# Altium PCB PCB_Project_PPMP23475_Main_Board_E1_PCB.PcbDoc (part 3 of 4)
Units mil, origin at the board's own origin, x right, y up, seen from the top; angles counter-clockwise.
Board outline 10826.77 x 2559.06 mil, 6 copper layers (Top Layer, Signal Layer 1, Signal Layer 2, Signal Layer 3, Signal Layer 4, Bottom Layer), stack 65.535 mil thick; 162 components, 91 nets, 425 pads, 676 vias.
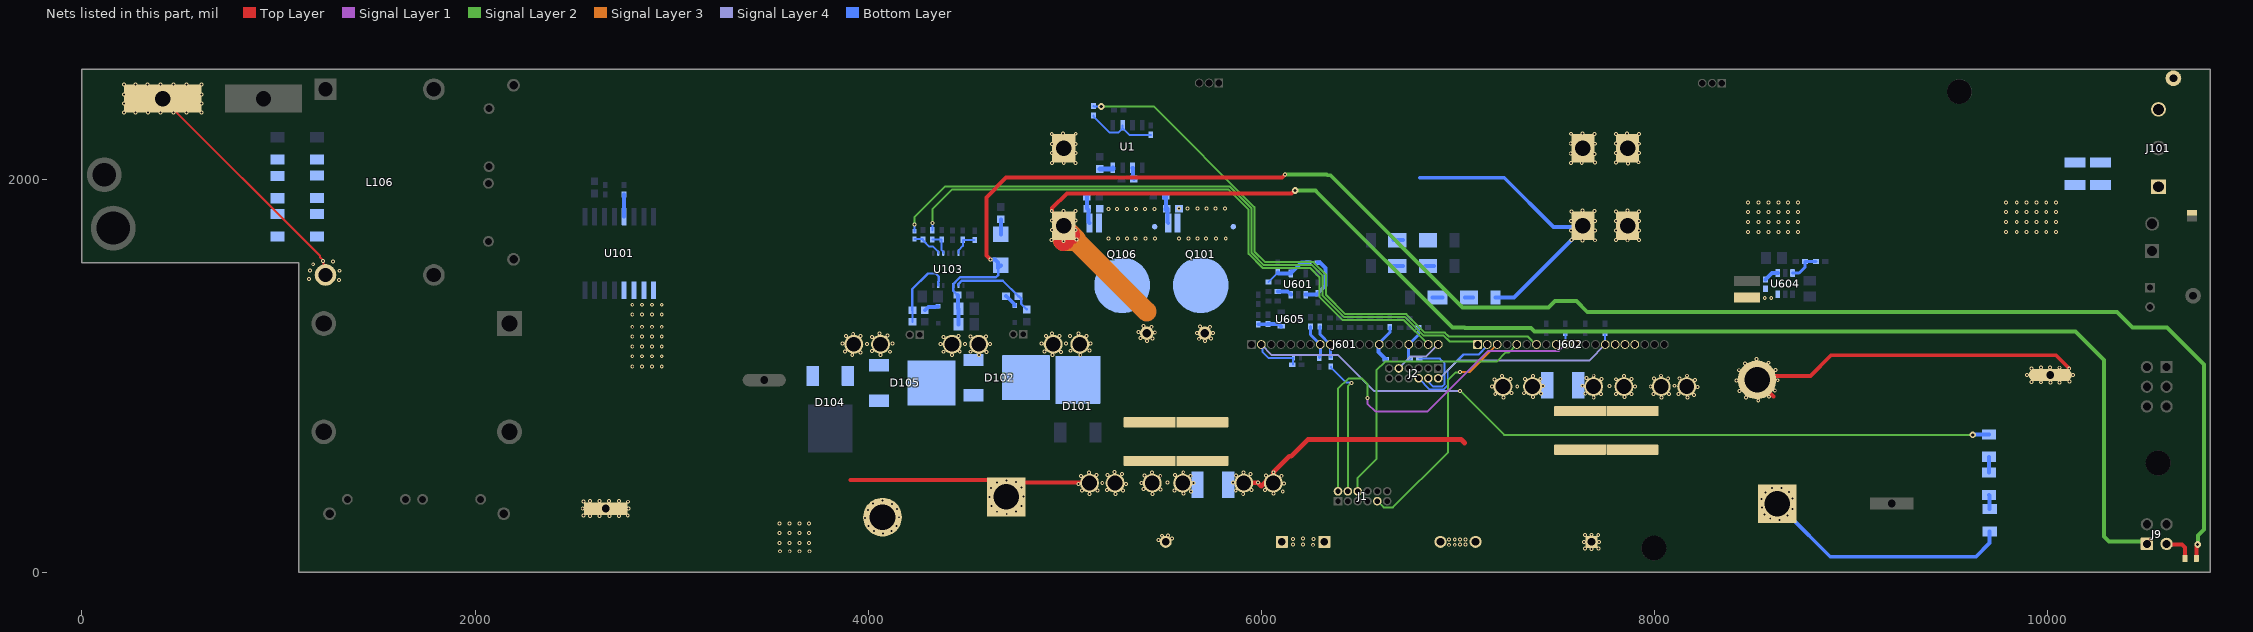
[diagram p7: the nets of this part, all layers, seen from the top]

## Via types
v1: diameter 20, hole 10, Top Layer to Bottom Layer, 563 vias
v2: diameter 20, hole 10, Top Layer to Bottom Layer, tented both sides, 103 vias
v3: diameter 34, hole 16, Top Layer to Bottom Layer, 10 vias

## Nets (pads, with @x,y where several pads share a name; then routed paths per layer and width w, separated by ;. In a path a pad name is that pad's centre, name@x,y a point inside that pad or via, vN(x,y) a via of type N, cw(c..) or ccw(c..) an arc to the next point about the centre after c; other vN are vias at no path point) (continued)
LS_TEMP1: J1.4 R623.1 | length 700.3
  Signal Layer 2 w10: J1.4@6440,413 6440,947 v2(6458,965)
  Bottom Layer w10: R623.1@6354,1048.38 6354,1044.44 6433,965.44 6457.56,965.44 v2(6458,965)
LS_TEMP2: J2.4 R637.1 | length 359.9
  Bottom Layer w10: R637.1@6803.62,1088 6908.49,1088 6933.05,1063.44 6933.05,958.76 6921.28,947 6872.72,947 6856.52,963.19 6856.52,981.48 J2.4@6850,988
LS_ZVS1: C612.1 J1.2 J602.10 | length 2044.2
  Signal Layer 1 w10: v1(6540,888) 6540,859 6581,818 6845.28,818 7155.21,1127.93 7513.27,1127.93 7545.32,1159.97 J602.10@7550,1159.97
  Signal Layer 2 w10: J1.2@6390,413 6390,934 6444,988 6512,988 6540,960 v1(6540,888) ; J602.10@7550,1150 J602.10@7550,1159
  Bottom Layer w10: C612.1@7547,1218.38 7548.5,1216.88 7548.5,1161.47 J602.10@7550,1159.97
  Bottom Layer w15: J602.10@7550,1159 J602.10@7550,1159.97
LS_ZVS2: C616.1 J2.2 J602.14 | length 981.4
  Signal Layer 4 w10: J2.2@6900,988 6907.07,988 6997.07,1078 7668.03,1078 J602.14@7750,1159.97
  Bottom Layer w10: C616.1@7748,1218.38 7749,1217.38 7749,1160.97 J602.14@7750,1159.97
  Bottom Layer w15: J602.14@7750,1159 J602.14@7750,1159.97
N_Wire: L106.2 pad.2 R112.1 R113.1 | length 1251.9
  Top Layer w10: pad.2@412.19,2411 1211.38,1611.81 1211.38,1603.32 1227,1587.71 v1(1227,1585) 1228.91,1583.09 1228.91,1498.06 L106.2@1229.41,1497.56
  other v1: 1309,1489 1155,1494 1310,1535 1160,1536 1177,1568 1277,1581 215,2340 273,2340 336,2340 401,2340 466,2340 533,2340 609,2340 215,2385 609,2385 215,2431 609,2432 215,2482 273,2482 335,2482 401,2482 466,2482 533,2482 609,2482
NetC115_1: C115.1 U101.13 | length 113.8
  Bottom Layer w20: C115.1@2758,1923.38 2759,1922.38 U101.13@2759,1810.01
NetC122_1: C122.1 R118.1 U103.2 | length 158.1
  Bottom Layer w10: R118.1@4235,1696.31 4277.06,1696.31 C122.1@4279,1694.38 4279,1690.44 4311.69,1657.75 4330.03,1657.75 4356.82,1630.96 U103.2@4356.82,1624.07
NetC123_1: C123.1 R120.1 U103.3 | length 122.2
  Bottom Layer w10: R120.1@4326,1693.38 4373,1693.38 C123.1@4374,1694.38 4374,1639.37 4382.41,1630.96 U103.3@4382.41,1624.07
NetC127_1: C127.1 R121.2 U103.6 | length 138.2
  Bottom Layer w10: U103.6@4459.18,1624.07 4459.18,1630.96 4460.09,1631.87 4460.09,1639.72 4482,1661.63 C127.1@4482,1692.38 4483,1691.38 R121.2@4542,1691.38
NetC128_1: C128.1 R122.1 U1.2 | length 369.1
  Bottom Layer w10: R122.1@5146,2325.38 5146,2321.44 5229.73,2237.71 5273.19,2237.71 U1.2@5295,2259.52 ; U1.2@5295,2275.27 U1.2@5295,2259.52 ; C128.1@5438,2226.38 5328.14,2226.38 U1.2@5295,2259.52
NetC623_1: C623.1 L601.1 U604.6
  other v2: 8561,1397 8594,1397
NetC623_2: C623.2 U604.1 | length 76.1
  Bottom Layer w20: C623.2@8565,1490.62 8597.51,1523.13 U604.1@8627.6,1523.13
NetD103_1: D103.1 R102.1 | length 66.3
  Bottom Layer w20: R102.1@4701.5,1406 4702.49,1406 4743.19,1365.3 4743.19,1360.12 D103.1@4745,1358.31
NetD106_1: D106.1 R111.1 | length 74.4
  Bottom Layer w20: R111.1@4288.5,1334 4289.48,1334 4306.01,1350.53 4343.74,1350.53 4345.71,1352.5 D106.1@4355.19,1352.5
NetD107_2: D107.2 R117.1 | length 76.8
  Bottom Layer w20: D107.2@4675,1719.74 R117.1@4675,1796.5
NetJ9_2: J9.2 R1.1 | length 157.7
  Top Layer w20: J9.2@10605,145.5 10607.5,143 10684.46,143 10699.46,128 R1.1@10699.46,72
NetQ101_1: Q101.1 R103.2 R104.2 | length 160.8
  Bottom Layer w20: R104.2@5505,1908.5 R104.2@5513.5,1917 5516,1914.5 5516,1848.5 R103.2@5516.5,1848 ; R103.2@5518.5,1850 5522.57,1845.93 5522.57,1781.7 Q101.1@5526.65,1777.63
  Bottom Layer w30: R103.2@5516.5,1848 R103.2@5518.5,1850
NetQ106_1: Q106.1 R101.2 R106.2 | length 140.2
  Bottom Layer w20: R101.2@5112.5,1912 5113.5,1911 5113.5,1851 R106.2@5114.5,1850 5120.9,1843.61 5120.9,1783.38 Q106.1@5126.65,1777.63
NetR102_2: R102.2 R105.2 U103.9 | length 437.4
  Bottom Layer w12: U103.9@4459.18,1460.69 4459.18,1467.39 4467.76,1475.97 4467.76,1476.79 4475.45,1484.48 4685.03,1484.48 4763.51,1406 R102.2@4764.5,1406 4765.48,1406 4778.18,1393.3 4778.18,1367.3 4806,1339.48 R105.2@4806,1338.5
NetR107_1: R107.1 R109.2
NetR108_1: R108.1 R110.2
NetR109_1: R109.1 R112.2
NetR110_1: R110.1 R113.2
NetR111_2: R111.2 R114.2 U103.12 | length 388.5
  Bottom Layer w12: R114.2@4225.5,1275 R111.2@4225.5,1334 4223.37,1336.13 4223.37,1440.63 4303.75,1521 4343.6,1521 4360,1504.6 4360,1481.4 4356.91,1478.32 4356.91,1460.78 U103.12@4356.82,1460.69
NetR119_2: R119.2 U1.6 | length 59.4
  Bottom Layer w20: U1.6@5345,2058.73 5346.81,2056.92 5346.81,2006.69 R119.2@5351.5,2002
NetR601_1: R601.1 R611.2 U601.1 | length 261.3
  Bottom Layer w20: U601.1@6225.4,1413.35 6280.24,1413.35 R611.2@6287,1420.11 6327,1460.11 6327,1548.49 6299,1576.49 R601.1@6286.62,1576.49
NetR601_2: R601.2 R609.2 R610.1 U601.4 | length 251
  Bottom Layer w10: R610.1@6036.38,1477.49 R609.2@6084,1525.11
  Bottom Layer w20: R609.2@6084,1525.11 6087.49,1521.62 U601.4@6150.6,1521.62 ; U601.4@6150.6,1522.18 6150.6,1529.5 6152.41,1531.31 6159.73,1531.31 6204.91,1576.49 R601.2@6239.38,1576.49
NetR602_1: R602.1 R606.2 | length 43.2
  Bottom Layer w20: R606.2@7035.09,1399 7076.91,1399 R602.1@7077.91,1400
NetR603_1: R603.1 R607.2 | length 42.8
  Bottom Layer w20: R607.2@6835.09,1559 R603.1@6877.91,1559
NetR604_1: R604.1 R608.2
NetR606_1: R606.1 R612.2 | length 49.8
  Bottom Layer w20: R612.2@6871.09,1399 R606.1@6920.91,1399
NetR607_1: R607.1 R613.2 | length 49.8
  Bottom Layer w20: R613.2@6671.09,1559 R607.1@6720.91,1559
NetR608_1: R608.1 R614.2 | length 49.8
  Bottom Layer w20: R614.2@6671.09,1691 R608.1@6720.91,1691
NetR616_1: R616.1 U601.3 | length 73.7
  Bottom Layer w20: R616.1@6083.62,1429.49 6134.46,1429.49 U601.3@6150.6,1413.35
NetR621_1: R621.1 R622.2 | length 73.1
  Bottom Layer w20: R622.2@9702,393.91 9705,390.91 R621.1@9705,322.09
NetR622_1: R622.1 R624.2 | length 83.7
  Bottom Layer w15: R624.2@9702,588.91 R624.2@9704,586.91
  Bottom Layer w20: R622.1@9702,508.09 R624.2@9702,588.91
NetR640_1: R640.1 R642.2 U605.1 | length 121
  Bottom Layer w20: R642.2@5985,1262.87 6033,1262.87 R640.1@6034,1263.87 6088.98,1263.87 U605.1@6100.76,1252.09
NetR641_1: R641.1 R643.2 U604.3 | length 160.6
  Bottom Layer w15: U604.3@8702.4,1523.13 8736.13,1523.13 8765.62,1552.62 R643.2@8765.62,1582 R641.1@8821.38,1582
Neutral: C106.1 C110.1 C124.1 D102.1 D102.3 D105.2 N_LF_1.1 N_LF_2.1 U101.1 U101.2 U101.3 U101.4 | length 2.8
  Bottom Layer w25: C106.1@6103.28,163 C106.1@6105.28,165
  other v1: 7679,119 7647,122 7715,122 6264,141 6161,142 6211,142 7642,155 7718,156 6161,170 6265,171 6212,172 7646,190 7714,190 7679,192 4564,1106 4427,1107 4602,1121 4384,1123 4521,1123 4466,1125 4368,1162 4492,1163 4620,1163 4383,1198 4521,1200 4599,1200 4459,1203
  other v2: 3551,108 3601,108 3651,108 3701,108 3550,150 3600,150 3650,150 3700,150 3550,200 3600,200 3650,200 3700,200 3550,250 3600,250 3650,250 3700,250 2800,1049 2850,1049 2900,1049 2950,1049 2800,1100 2850,1100 2900,1100 2950,1100 2800,1150 2850,1150 2900,1150 2950,1150 2800,1200 2850,1200 2900,1200 2950,1200 2800,1250 2850,1250 2900,1250 2950,1250 2800,1312 2850,1312 2900,1312 2950,1312 2800,1362 2850,1362 2900,1362 2950,1362
PFCG_1H: J1.9 J602.3 | length 1182.4
  Signal Layer 2 w10: J1.9@6590,363 6622.05,330.95 6668.95,330.95 6950,612 6950,980.28 6986.8,1017.09 7009.09,1017.09 v1(7011,1019)
  Signal Layer 3 w10: v1(7011,1019) 7059.03,1019 J602.3@7200,1159.97
PFCG_1L: J1.6 J602.5 | length 1424
  Signal Layer 2 w10: J1.6@6490,413 6490,482 6584.95,576.95 6584.95,1027.95 6630,1073 7196.72,1073 7241.72,1118 7258.03,1118 J602.5@7300,1159.97
PFCG_2H: J2.9 J601.20 | length 250.5
  Signal Layer 4 w10: J2.9@6700,1038 6760.99,1098.99 6839.01,1098.99 J601.20@6900,1159.97
PFCG_2L: J2.6 J602.2 | length 527.2
  Signal Layer 4 w10: J602.2@7143.48,1152.48 J602.2@7150,1159
  Bottom Layer w10: J2.6@6800,988 6858,930 6925.5,930 6948.5,953 6948.5,1028.99 7028.5,1109 7106.1,1109 7150,1152.9 J602.2@7150,1159.97
PGND: C2.1 C3.1 C4.1 C5.1 C101.1 C102.1 C130.2 C131.2 D104.1 D104.3 D105.1 D105.3 J101.1 NT1.1 pad.1@4994.89,2157.61 pad.1@7635.89,2158 pad.1@7863.11,2158 PGND_LF_1.1 PGND_LF_2.1 PGND_PH1_1.1 PGND_PH1_2.1 PGND_PH2_1.1 PGND_PH2_2.1
  other v1: 5446,400 5604,402 5643,412 5559,418 5487,423 5400,424 5654,455 5390,456 5522,457 5486,492 5639,492 5406,494 5562,495 5443,509 5603,510 7691,891 7848,892 7729,908 7884,908 7805,909 7648,910 7900,947 7771,948 7634,950 7804,983 7730,985 7884,985 7655,989 7846,1000 7691,1001 3919,1107 4062,1107 3960,1120 4110,1123 3883,1124 4020,1126 3995,1163 3870,1165 4123,1165 4019,1197 3888,1202 3960,1202 4098,1206 3924,1214 4058,1215 8475,1733 8530,1733 8580,1733 8630,1733 8680,1733 8730,1733 9788,1733 9843,1733 9893,1733 9943,1733 9993,1733 10043,1733 8475,1783 8530,1783 8580,1783 8630,1783 8680,1783 8730,1783 9788,1783 9843,1783 9893,1783 9943,1783 9993,1783 10043,1783 8475,1833 8530,1833 8580,1833 8630,1833 8680,1833 8730,1833 9788,1833 9843,1833 9893,1833 9943,1833 9993,1833 10043,1833 8475,1883 8530,1883 8580,1883 8630,1883 8680,1883 8730,1883 9788,1883 9843,1883 9893,1883 9943,1883 9993,1883 10043,1883 7865,2081 7630,2082 4995,2083 5055,2083 4935,2084 7576,2084 7697,2085 7805,2086 7919,2087 7696,2130 7574,2131 7804,2134 7922,2134 4934,2135 5056,2135 4935,2179 5056,2180 7697,2181 7922,2181 7574,2182 7804,2182 7695,2230 7922,2230 4934,2231 7805,2231 5056,2232 7575,2232 4992,2233 7634,2233 7861,2234
PRI_FAULT: J602.15
PWM1A: J601.19 R120.2 | length 3189.9
  Signal Layer 2 w10: v1(4327,1777) 4327,1849 4427,1949 5832,1949 5935,1846 5935,1620.57 6006.57,1549 6248.7,1549 6295.56,1502.14 6295.56,1403.44 6414.84,1284.16 6725.81,1284.16 J601.19@6850,1159.97
  Bottom Layer w10: R120.2@4326,1740.62 4326.5,1741.12 4326.5,1776.5 v1(4327,1777)
PWM1B: J602.1 R118.2 | length 3526.3
  Signal Layer 2 w10: v1(4235,1771) 4235,1807 4392,1964 5824.79,1964 5838.21,1964 5950,1852.21 5950,1838.79 5950,1626.79 6012.79,1564 6258.33,1564 6310.56,1511.76 6310.56,1409.65 6421.05,1299.16 6732.02,1299.16 6826.19,1205 6927.89,1205 6957.86,1175.04 7084.94,1175.04 J602.1@7100,1159.97
  Bottom Layer w10: R118.2@4235,1735.69 v1(4235,1771)
RELAY_CTRL: J602.7 R122.2 | length 2948.6
  Signal Layer 2 w10: v3(5186,2371) 5452.43,2371 5965,1858.43 5965,1633 6019,1579 6264.54,1579 6329,1514.54 6329,1412.43 6427.26,1314.16 6738.24,1314.16 6832.4,1220 6934.11,1220 6953.61,1200.5 7354.79,1200.5 7396.29,1159 J602.7@7400,1159
  Bottom Layer w10: R122.2@5146,2372.62 5147.62,2371 v3(5186,2371)
SCI_RX0: J602.16
SCI_TX0: J602.17 | length 9
  Signal Layer 2 w10: J602.17@7900,1159 J602.17@7900,1168
SDC: J602.9
SDD: J602.11
SW1: L1.1 L102.1 SW_PH1_1.1 SW_PH1_2.1 | length 1235.6
  Top Layer w20: 3910.41,471.59 4643.41,471.59 v1(4656,459) 4690.37,459 4702.96,471.59 4713.55,461 v1(4752,461) 4756,457 5104.05,457 SW_PH1_1.1@5122.05,439
  other v1: 2586,287 2684,287 2733,287 2633,288 2551,290 2777,290 4705,298 4656,309 4753,311 2781,325 2548,326 4627,338 4779,338 2778,360 2551,361 2633,363 2733,363 2586,364 2682,364 4617,384 4790,386 5127,400 5258,400 5088,417 5166,417 5296,417 5214,420 4625,430 4781,433 5311,450 5070,451 5191,455 4703,467 5083,490 5218,495 5161,497 5292,500 5124,509 5253,511
SW2: L2.2 L104.2 SW_PH2_1.1 SW_PH2_2.1 | length 1881.2
  Top Layer w20: 8606.15,895 8543.35,957.8 8543.35,999.65 8793.65,999.65 8899.07,1105.07 10042.93,1105.07 v1(10110,1038) 10100.51,1028.51 10100.51,1024.63 10080.65,1004.77 L2.2@10013.54,1004.77
  other v1: 8528,875 8036,891 8168,891 8466,891 8583,894 8201,904 7994,907 8123,908 8074,909 8433,923 8612,925 8218,944 7981,946 8103,950 10014,967 10061.3,966.74 9967.3,967.74 9917,970 10111,972 8417,976 8627,978 8207,980 7997,987 8070,987 8127,988 8033,1001 8166,1001 9896,1005 10130,1005 8429,1029 8615,1030 9917,1038 10013,1042 10060.3,1041.74 9966.3,1042.74 8460,1064 8581,1067 8520,1085
TEMP1: C608.1 J601.8 R620.2 | length 207.7
  Bottom Layer w15: C608.1@6250,1250.87 6250,1209.97 J601.8@6300,1159.97 J601.8@6300,1159 ; R620.2@6295,1092.62 6295,1096.56 6300,1101.56 J601.8@6300,1159 ; J601.8@6312.27,1160.61 6310,1158.35 6310,1149 J601.8@6300,1159
TEMP2: C610.1 J601.9 R623.2 | length 178.4
  Bottom Layer w15: C610.1@6298,1250.87 6298,1211.97 J601.9@6350,1159.97 6350,1159 6352,1157 6352,1097.62 R623.2@6354,1095.62
TEMP3: C613.1 J601.14 R626.2 | length 205.7
  Bottom Layer w15: J601.14@6600,1159 6600,1168 6654,1222 C613.1@6654,1248.87
  Bottom Layer w20: J601.14@6600,1159 6596.01,1155.01 6596.01,1122.37 6627.63,1090.75 6627.63,1086.81 6629.44,1085 R626.2@6633.38,1085
TEMP4: C615.1 J601.17 R637.2 | length 183.4
  Bottom Layer w15: R637.2@6756.38,1088 6753.81,1088 6749.5,1092.31 6749.5,1158.5 6750,1159 J601.17@6750,1159.97 6800.38,1210.35 C615.1@6800.38,1246
Vbulk: C2.2 C3.2 C4.2 C5.2 C130.1 C131.1 D101.2 D102.2 Q101.9 Q106.9 RT1.1 VB_LF_1.1 VB_LF_2.1 VB_PH1_1.1 VB_PH1_2.1 VB_PH2_1.1 VB_PH2_2.1 | length 1209
  Top Layer w25: 5962.5,456.5 5982.5,456.5 6000,439 6038.5,477.5 6064.16,477.5 6061,480.66 v1(6061,510) 6142.5,591.5 6152.5,591.5 6238.5,677.5 7015.77,677.5 7034.27,659
  other v1: 5908,400 6062,401 6109,411 5870,417 5951,419 6018,420 6116,452 5855,458 5984,458 6102,492 5871,493 6023,493 5944,500 5910,509 7232,891 7381,892 7190,908 7422,911 7337,912 7273,914 7174,946 7302,947 7434,948 7187,982 7268,984 7341,984 7419,985 7225,1000 7383,1000 4937,1106 5079,1106 4981,1121 4897,1124 5030,1128 5125,1130 5130,1165 4882,1166 5007,1166 5714,1177 5683,1189 5743,1191 4904,1203 4974,1203 5026,1203 5110,1203 5070,1215 4936,1216 5672,1218 5754,1218 5739,1250 5687,1251
Vbulk_out: C1.2 C101.2 C102.2 J9.1 J101.3 pad.1@4994.89,1763.91 pad.1@7635.89,1764.3 pad.1@7863.11,1764.3 Q101.2 Q101.3-4-5-6-7-8 Q106.2 Q106.3-4-5-6-7-8 R103.1 R106.1 R602.2 RT1.2 TP101.1 U1.8 | length 9391.1
  Top Layer w20: v1(4934,1838) 4934.75,1838.75 4934.75,1853.25 5010.51,1929 6154.21,1929 6168.21,1943 v3(6172,1943)
  Top Layer w25: J9.1@10502.5,143 J9.1@10505,145.5
  Top Layer w100: v1(4993,1685) 5021.51,1713.51 pad.1@5021.51,1723.51 ; pad.1@4994.89,1763.91 4994.89,1750.13 pad.1@5021.51,1723.51 ; pad.1@5026.51,1718.51 pad.1@5021.51,1723.51
  Signal Layer 2 w20: v3(6172,1943) 6275.28,1943 6287,1931.28 6287,1930.75 6972.25,1245.5 7033.5,1245.5 7036,1243 7372.4,1243 7388.78,1226.62 10141.38,1226.62 10287.5,1080.5 10287.5,182.5 10313,157 10493.5,157 J9.1@10505,145.5
  Signal Layer 3 w100: pad.1@4994,1751.02 pad.1@4994,1764.5 ; pad.1@4994.89,1763.91 4994.89,1750.13 5021.51,1723.51 5021.51,1719.51 4990,1688 v1(4993,1685) 5060.02,1685 5417,1328.02 ; pad.1@5025.5,1727.5 v1(5059,1694) ; pad.1@5026.51,1718.51 pad.1@5052.55,1692.48
  Bottom Layer w20: 6808,2008 7236,2008 7486,1758 7629.59,1758 pad.1@7635.89,1764.3 7635.89,1750.52 7577.74,1692.37 7284.37,1399 R602.2@7191.09,1399
  Bottom Layer w25: C1.2@5178,2052.5 5244.31,2052.5 5245,2053.19 U1.8@5245,2058.73
  other v1: 5418,1178 5447,1190 5386,1192 5458,1221 5376,1223 5442,1250 5401,1255 7633,1689 7697,1690 7863,1690 7578.72,1691.38 7804,1691 7922,1691 4933,1692 5222,1698 5270,1698 5316,1698 5359,1698 5411,1698 5460,1698 5581,1699 5629,1699 5675,1699 5718,1699 5770,1699 5819,1699 7575,1739 7697,1739 7804,1740 7921,1740 5056,1742 4935,1743 7804,1787 7922,1787 7575,1788 7697,1788 4934,1790 5056,1790 7577,1837 7804,1837 7922,1837 7696,1838 4994,1839 5055,1839 7633,1841 7862,1841 5222,1850 5265,1850 5317,1850 5362,1850 5408,1850 5456,1850 5581,1851 5624,1851 5676,1851 5721,1851 5767,1851 5815,1851
Vcb: C106.2 C110.2 C124.2 L102.2 L104.1 R621.2 | length 1203.1
  Bottom Layer w20: v1(8676,289) 8685.22,289 8894.22,80 9636,80 9705,149 R621.2@9705,207.91
  other v1: 6955.15,141 6984,141 7011.08,142 7039,142 5477,165 6955.15,167 6984,167 7011.08,168 7039,168 5546,173 5494,187 5525,189 4076,199 4029,211 4118,211 4001,236 4144,237 8637,268 8589,274 3985,278 4156,281 8560,295 3999,317 4146,323 8702,323 8546,331 4122,348 4025,350 4074,366 8545,374 8702,376 8564,407 8684,410 8597,429 8646,431
Vcb_SENSE: C624.2 J601.2 R624.1 R625.2 | length 4138.3
  Signal Layer 2 w10: v1(7011,924) 7235,700 v3(9619,700)
  Signal Layer 4 w10: J601.2@6000,1159.97 6053.94,1106.04 6390.96,1106.04 6573,924 v1(7011,924)
  Bottom Layer w10: J601.2@6000,1159.97 6005.21,1154.76 6005.21,1121.79 6037,1090 R625.2@6162.97,1090 ; C624.2@6161.16,1057.81 6161.16,1088.19 R625.2@6162.97,1090 ; R625.2@6163.28,1090 R625.2@6162.97,1090
  Bottom Layer w20: v3(9619,700) 9628,700 9631.09,703.09 R624.1@9702,703.09
VDDB: C116.1 C118.1 C119.2 D107.1 R1.2 U103.10 | length 8590.2
  Top Layer w20: v1(4622,1592) 4601,1613 4601,1908 4702,2009 6106.54,2009 v1(6121.54,2024) ; R1.2@10756.54,72 10756.54,131.75 10763,138.21 v3(10763,142) v3@10762,143
  Signal Layer 2 w20: v1(6121.54,2024) 6333,2024 6336,2021 6350.89,2021 7022.89,1349 7461,1349 7493,1381 7603,1381 7658,1326 10352,1326 10432,1246 10608,1246 10795,1059 10795,217.79 10765.68,188.47 10765.68,144.68 v3(10763,142)
  Bottom Layer w12: C119.2@4454.5,1412 4453.52,1412 4440.82,1424.7 4440.82,1425.69 4433.59,1432.91 U103.10@4433.59,1460.69 4433.59,1467.39 4442.17,1475.97 4442.17,1476.79 4466.86,1501.48 4650.48,1501.48 4660.92,1511.92 D107.1@4660.92,1548.18
  Bottom Layer w20: C119.2@4454.5,1412 4457.25,1409.25 4457.25,1343.75 C116.1@4460,1341 C118.1@4460,1262 ; v1(4622,1592) 4622.37,1591.63 4645.63,1591.63 4660.92,1576.34 4660.92,1548.18 D107.1@4675,1562.26
pads on no net: J01.1 J01.2 J01.3 J3.1 J3.2 J3.3 J101.2 J601.3 J601.4 J601.5 J601.7 J602.13 J602.20 U101.9 U101.11 U101.14 U101.16 U103.5

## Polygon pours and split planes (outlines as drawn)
5VP on Top Layer "Top Layer-No Net 14" (solid, remove dead copper, pour order 981): 19 vertices, not listed, extent 5844,876 10544,1574.8
Vbulk on Top Layer "Top Layer-No Net 3" (solid, pour order 913): 28 vertices, not listed, extent 4814,332 8051,1314
Vbulk_out on Top Layer "Top Layer-No Net" (solid, remove dead copper, pour order 989): 20 vertices, not listed, extent 4911,1149.58 10785,2559.06
12VP on Top Layer "NONET_L-01_P-001" (solid, pour order 1038): 4680,1913 4661,1894 4661,1591.71 4626.29,1557 4345,1557 4322,1534 4322,1455 4349,1428 4737,1428 4813,1504 4813,1866.47 4755.97,1913
Neutral on Top Layer "Top Layer-No Net 4" (solid, pour order 998): 3640,751 3787,604 4646,604 4646,1365 4378,1365 3992,1751 2783,1751 2783,1032.28 3278.96,1032.28 3278.96,1084 3598,1084 3640,1042
AGND on Top Layer "Bottom Layer-No Net 22" (solid, pour order 1004): 10325,1617 10518,1810 10795,1810 10795,1286 10795,804 10546.47,804 10546.47,1069.47 10494.94,1121 10325,1121
PGND on Top Layer "Bottom Layer-No Net 23" (solid, pour order 985): 5809,575 5780,604 5368,604 5347,583 5347,382 5397,332 5734,332 5809,407
PGND on Top Layer "Top Layer-No Net 17" (solid, pour order 984): 7997.5,845.5 7921,922 7921,1027 7483,1027 7483,790 7997.5,790
SW2 on Top Layer "Top Layer-No Net 2" (solid, remove dead copper, pour order 917): 9920,1266 8442,1266 8224,1048 8033,1048 7961,976 7961,859 8056,764 8721,764 8868,911 10110,911 10162,963 10162,1024
Neutral on Top Layer "Top Layer-No Net 19" (solid, pour order 1082): 3530.6,84 3530.6,270.43 3732,270.43 3732,84
AC_N1 on Top Layer "Top Layer-No Net 19" (solid, pour order 1081): 2578.6,1092 2578.6,1373.43 2717.6,1373.43 2717.6,1092
PGND on Top Layer "Top Layer-No Net 19" (solid, pour order 1080): 3860.61,1226 4119.61,1226 4119.61,1087 3860.61,1087
PGND on Top Layer "Bottom Layer-No Net 22" (solid, pour order 1014): 10301,1539 10301,1629 10491,1819 10760,1819 10793,1852 10793,2015 10769,2039 8612,2039 8430,1857 8430,1681 8463,1648 8858,1648 8967,1539
PGND on Top Layer "Top Layer-No Net 15" (solid, pour order 1003): 5339,2054 5408.77,2123.77 6313.23,2123.77 6428,2009 7889,2009 7988,2108 7988,2413 7892,2509 4891,2509 4891,2054
AC_L1 on Top Layer "Top Layer-No Net 5" (solid, remove dead copper, pour order 918): 21 vertices, not listed, extent 1145,212 3603,1092
SW1 on Top Layer "Top Layer-No Net 1" (solid, remove dead copper, pour order 916): 5317.58,381.28 5316.98,497.66 5241.64,573 3756.34,573 3088.5,573 2484,573 2484,53 3236.34,53 3505.34,322 3916.95,322 4012.98,418.02 4139.98,418.02 4236,322 5258.3,322
Vcb on Top Layer "Top Layer-No Net 11" (solid, remove dead copper, pour order 959): 24 vertices, not listed, extent 3973,5 8765,553
Neutral on Top Layer "Top Layer-No Net 19" (solid, pour order 915): 6091,185 6325,185 6341,169 6341,137 6328,124 6096,124 6082,138 6082,176
N_Wire on Top Layer "Top Layer-No Net 6" (solid, remove dead copper, pour order 919): 25 vertices, not listed, extent 101,1423 1341,2514
L_Wire on Top Layer "Top Layer-No Net 7" (solid, remove dead copper, pour order 920): 1291,2543 1355,2479 1355,2298 1267,2210 849,2210 720,2339 720,2514 749,2543
AC_N on Top Layer "Top Layer-No Net 8" (solid, remove dead copper, pour order 931): 2133,1747 1767,1747 1715,1695 1715,1398 1765,1348 1948,1165 2290,1165 2348,1223 2348,1532
AC_L on Top Layer "Top Layer-No Net 9" (solid, remove dead copper, pour order 932): 19 vertices, not listed, extent 1131,1111 2239.5,2536
AC_N1 on Top Layer "Top Layer-No Net 16" (solid, pour order 982): 2000,712 2000,300 2050,250 2214,250 2272,308 2272,708 2202,778 2066,778
AC_L1 on Top Layer "Top Layer-No Net 20" (solid, pour order 1024): 9148,465 9606,465 9606,131 9121,131 9060,192 9060,377
Neutral on Top Layer "Signal Layer 1-No Net 3" (solid, pour order 914): 7628.5,218 7744.5,218 7744.5,103 7628.5,103
NetC623_1 on Top Layer "Top Layer-No Net 13" (solid, pour order 964): 8404,1427 8595,1427 8605,1417 8605,1376 8595,1366 8406,1366 8396,1376 8396,1419
EARTH on Top Layer "Top Layer-No Net 10" (solid, remove dead copper, pour order 954): 34,2114 151,2114 205,2060 205,1878 281,1802 281,1678 205,1602 33,1602 6,1629 6,2085
AC_L1 on Bottom Layer "Bottom Layer-No Net" (solid, pour order 986): 24 vertices, not listed, extent 3299,123 9612,1057
AGND on Bottom Layer "NONET_L-01_P-001" (solid, pour order 1084): 6830,1242 7834,1242 7941,1135 7974,1135 7974,1237 7893,1318 6830,1318
Vbulk_out on Bottom Layer "Bottom Layer-No Net 6" (solid, pour order 991): 21 vertices, not listed, extent 4871,1620 10790,2559.05
AGND on Bottom Layer "NONET_L-01_P-001" (solid, pour order 1025): 2445,2540 2445,1574.8 4894,1574.8 4894,2265.06 5113,2265.06 5113,2227.88 5503.5,2227.88 5502.83,2540
Vbulk_out on Bottom Layer "Signal Layer 4-No Net" (solid, pour order 1083): 5338,1285 5338,1149.58 5501,1149.58 5501,1285
EARTH on Bottom Layer "Bottom Layer-No Net 20" (solid, pour order 1075): 6,2135.5 267,2135.5 267,1626 6,1626
SW1 on Bottom Layer "Bottom Layer-No Net 23" (solid, pour order 1051): 2801,388 2525,388 2525,266 2801,266
AGND on Bottom Layer "Bottom Layer-PGND" (solid, pour order 1023): 33 vertices, not listed, extent 8613,1283 10795,1819
PGND on Bottom Layer "NONET_L-01_P-001" (solid, pour order 1020): 3651,975 3651,1244 4136,1244 4136,801 3825,801
Neutral on Bottom Layer "Bottom Layer-Neutral" (solid, remove dead copper, pour order 1045): 19 vertices, not listed, extent 2737,15 7776,1493
Vbulk on Bottom Layer "Bottom Layer-No Net 24" (solid, pour order 978): 5831,528 6109,528 6133,504 6133,375 5844.06,375 5809,410.06 5809,506
5VP on Bottom Layer "NONET_L-01_P-001" (solid, pour order 1037): 5266,2364.69 5260.53,2371 5226.62,2371 5226.62,2370.62 5202,2346 5202,2289 5237.97,2253.03 5257.03,2253.03 5266,2262
Vcb on Bottom Layer "Bottom Layer-No Net 27" (solid, pour order 1009): 8430,474 8729,474 8766,437 8766,199.5 8683,116.5 8413.5,116.5 8363,167 8363,407
12VP on Bottom Layer "NONET_L-01_P-001" (solid, pour order 1028): 8658.19,1436.98 8824.02,1436.98 8832,1429 8832,1344 8819,1331 8657,1331 8640,1348 8640,1433
PGND on Bottom Layer "Bottom Layer-PGND" (solid, pour order 1022): 10408.93,1584 10408.93,1731.64 10505.28,1828 10795,1828 10795,1919 10706,2008 10501,2008 8582,2008 8415,1841 8415,1698 8465,1648 8858,1648 8951,1555 10381.03,1556.1
Vbulk on Bottom Layer "Bottom Layer-No Net 2" (solid, pour order 990): 5884,867 5884,1657 4776,1657 4776,1453 4841,1388 4841,1139.82 4698,996.82 4698,867
Neutral on Bottom Layer "NONET_L-01_P-001" (solid, pour order 1021): 4195,1100 4336,1100 4353,1117 4353,1198 4363,1208 4636,1208 4636,879.78 4554.28,809 4227.79,809 4148.35,888.44 4147.44,1052.44
AC_N1 on Bottom Layer "Bottom Layer-No Net 3" (solid, remove dead copper, pour order 922): 2535,1493 2481,1439 2481,1276 1961,756 1961,306 2058,209 2242,209 2295,262 2295,584 2725,1014 2725,1484 2716,1493
L_Wire on Bottom Layer "Bottom Layer-No Net 11" (solid, remove dead copper, pour order 929): 749,2543 1285,2543 1337,2491 1337,2286 1236,2185 876,2185 798,2263 720,2341 720,2514
N_Wire on Bottom Layer "Bottom Layer-No Net 12" (solid, remove dead copper, pour order 930): 23 vertices, not listed, extent 106,1410 1342,2515
AC_N on Bottom Layer "Top Layer-No Net 8" (solid, remove dead copper, pour order 957): 2133,1747 1767,1747 1715,1695 1715,1398 1765,1348 1949,1164 2266.36,1164 2348,1245.64 2348,1532
AC_L on Bottom Layer "Top Layer-No Net 9" (solid, remove dead copper, pour order 961): 19 vertices, not listed, extent 1131,1111 2239.5,2536
AC_L1 on Bottom Layer "Bottom Layer-No Net 20" (solid, pour order 962): 1185,824.5 1338,824.5 1405,757.5 1405,279.5 1341,215.5 1199,215.5 1144,270.5 1144,783.5
SW2 on Bottom Layer "Top Layer-No Net 2" (solid, remove dead copper, pour order 1012): 9973,1231 8307,1231 8124,1048 8003,1048 7961,1006 7961,885 8036,810 8767,810 10009,810 10162,963 10162,1042
PGND on Bottom Layer "Bottom Layer-No Net 23" (solid, pour order 972): 7915.72,1027 7602,1027 7544,969 7544,874 7914.67,874
Vbulk on Bottom Layer "Signal Layer 4-No Net" (solid, pour order 979): 7179,1033 7151,1005 7151,918 7194,875 7474,875 7474,968 7409,1033
SW2 on Bottom Layer "Bottom Layer-No Net 26" (solid, pour order 983): 8056,980 8087,1011 8347,1011 8375,983 8375,841 8345,811 8067,811 8056,822
Vcb on Bottom Layer "Bottom Layer-No Net 21" (solid, remove dead copper, pour order 921): 6891,176 7111,176 7111,134 6891,134
SW1 on Bottom Layer "Bottom Layer-No Net 25" (solid, pour order 980): 4668.12,524 4632,482.93 4632,361 4678,315 5244,315 5317.35,388.35 5317.35,497.29 5290.64,524
AGND on Bottom Layer "Bottom Layer-No Net 17" (solid, pour order 949): 6484,1225.16 6484,1145 6492,1137 6511.29,1137 6518.45,1144.16 6518.45,1183.61 6556,1221.16 6572,1237.16 6572,1309.16 6567,1314.16 6488,1314.16 6484,1310.16
5VP on Bottom Layer "Bottom Layer-No Net 15" (solid, pour order 940): 8510,1635 8414,1539 8414,1514 8425,1503 8519,1503 8539,1523 8539,1541 8553,1555 8587,1555 8595,1563 8595,1629 8589,1635
NetC623_1 on Bottom Layer "Bottom Layer-No Net 14" (solid, pour order 933): 8551,1459 8578,1459 8602,1435 8638,1435 8640,1433 8640,1396 8630,1386 8554,1386 8548,1392 8548,1456
NetR107_1 on Bottom Layer "Bottom Layer-No Net 10" (solid, remove dead copper, pour order 923): 1028,2129 1032,2125 1032,1993 1027,1988 963,1988 958,1993 958,2125 962,2129
NetR108_1 on Bottom Layer "Bottom Layer-No Net 10" (solid, remove dead copper, pour order 924): 1229,2129 1233,2125 1233,1993 1228,1988 1164,1988 1159,1993 1159,2125 1163,2129
NetR109_1 on Bottom Layer "Bottom Layer-No Net 10" (solid, remove dead copper, pour order 925): 1028,1934 1032,1930 1032,1798 1027,1793 963,1793 958,1798 958,1930 962,1934
NetR110_1 on Bottom Layer "Bottom Layer-No Net 10" (solid, remove dead copper, pour order 927): 1229,1934 1233,1930 1233,1798 1228,1793 1164,1793 1159,1798 1159,1930 1163,1934
PGND on Bottom Layer "Bottom Layer-No Net 23" (solid, pour order 974): 5715.56,525 5375,525 5375,370.56 5715.56,370.56
Vbulk on Signal Layer 2 "Signal Layer 2-No Net 2" (solid, pour order 977): 7171,1015 7426,1015 7464,977 7464,923 7413,872 7184,872 7151,905 7151,995
PGND on Signal Layer 2 "Bottom Layer-No Net 22" (solid, remove dead copper, pour order 971): 8431,2026 8055,1650 7531,1650 7451.81,1729.19 7451.81,1995.81 7512,2056 7925,2056 8002,2133 8002,2540 6597,2540 6597,1884 7051,1430 10805,1430 10805,1946 10725,2026
5VP on Signal Layer 2 "NONET_L-01_P-001" (solid, pour order 1029): 39 vertices, not listed, extent 2580.91,277 6484.13,2353
N_Wire on Signal Layer 2 "Bottom Layer-No Net 23" (solid, pour order 1078): 631,2321.77 631,2496.65 173.5,2496.65 173.5,2321.77
AC_L on Signal Layer 2 "Bottom Layer-No Net 23" (solid, pour order 1077): 2236,2422 2236,2541 2138,2541 2138,2422
AC_L on Signal Layer 2 "Bottom Layer-No Net 23" (solid, pour order 1076): 1883,2358.12 1883,2533 1694,2533 1694,2358.12
PGND on Signal Layer 2 "Bottom Layer-No Net 23" (solid, pour order 1066): 5076,2063 5076,2244 4913,2244 4913,2063
AC_L1 on Signal Layer 2 "Bottom Layer-No Net 23" (solid, pour order 1065): 1379.53,200 1379.53,794 1122,794 1122,200
AC_L on Signal Layer 2 "Bottom Layer-No Net 23" (solid, pour order 1064): 1339,1181.12 1339,1347 1133,1347 1133,1181.12
N_Wire on Signal Layer 2 "Bottom Layer-No Net 23" (solid, pour order 1063): 1330,1449.12 1330,1615 1141,1615 1141,1449.12
SW1 on Signal Layer 2 "Bottom Layer-No Net 23" (solid, pour order 1062): 2792,265 2792,384 2517,384 2517,265
AC_L1 on Signal Layer 2 "Bottom Layer-No Net 23" (solid, pour order 1061): 3657.61,876.82 3660.74,1042.7 3302,1042.7 3302,876.82
PGND on Signal Layer 2 "Bottom Layer-No Net 23" (solid, pour order 1060): 4172.61,1079.12 4175.74,1245 3817,1245 3817,1079.12
Vbulk_out on Signal Layer 2 "Bottom Layer-No Net 13" (solid, pour order 928): 8324.05,2559.05 8064,2299 8064,2146 7865,1947 7604,1947 7542,1885 7542,1714 7590,1666 8028,1666 8438,2076 10697,2076 10786,2165 10786,2424 10650.95,2559.05
Neutral on Signal Layer 2 "Signal Layer 2-Neutral" (solid, remove dead copper, pour order 1015): 28 vertices, not listed, extent 2746,15 7776,1378
Vcb on Signal Layer 2 "Bottom Layer-No Net 21" (solid, remove dead copper, pour order 994): 6895,176 7111,176 7111,134 6895,134
Vbulk_out on Signal Layer 2 "NONET_L-01_P-001" (solid, pour order 1035): 4965,1908 4960,1908 4891,1839 4891,1674 4931.65,1633.35 5837.35,1633.35 5901,1697 5901,1844.35 5837.35,1908
Vbulk on Signal Layer 2 "Signal Layer 2-No Net 5" (solid, pour order 987): 4841,1282 5778,1282 5778,1058 5933,903 6175,903 6205,873 6205,356 6178,329 5875,329 5854,350 5854,512 5778,588 5220,588 4841,967
L_Wire on Signal Layer 2 "Top Layer-No Net 7" (solid, remove dead copper, pour order 936): 1291,2543 1355,2479 1355,2298 1267,2210 849,2210 720,2339 720,2514 749,2543
AC_N on Signal Layer 2 "Top Layer-No Net 8" (solid, remove dead copper, pour order 942): 2133,1747 1767,1747 1715,1695 1715,1398 1765,1348 1949,1164 2266.36,1164 2348,1245.64 2348,1532
AC_N1 on Signal Layer 2 "Bottom Layer-No Net 3" (solid, remove dead copper, pour order 952): 2499,1378 2479,1358 2479,1278 1959,758 1959,308 2056,211 2240,211 2293,264 2293,586 2723,1016 2723,1358 2703,1378
EARTH on Signal Layer 2 "Signal Layer 2-No Net" (solid, pour order 926): 24 vertices, not listed, extent 7,321 2121,2114
PGND on Signal Layer 2 "Bottom Layer-No Net 23" (solid, pour order 969): 7931.74,861.12 7931.74,1027 7573,1027 7573,861.12
SW2 on Signal Layer 2 "Top Layer-No Net 2" (solid, remove dead copper, pour order 1011): 9968,1218 8348,1218 8178,1048 8033,1048 7963,978 7963,833 8032,764 8721,764 8868,911 10099,911 10159,971 10159,1027
AC_L1 on Signal Layer 2 "Top Layer-No Net 20" (solid, pour order 1007): 9092,409 9518,409 9599,328 9599,183 9547,131 9121,131 9060,192 9060,377
SW1 on Signal Layer 2 "Bottom Layer-No Net 23" (solid, pour order 1013): 5318,532 4578,532 4578,284 5318,284
Vcb on Signal Layer 2 "Bottom Layer-No Net 27" (solid, pour order 1001): 8378,476 8743,476 8760,459 8760,187 8695,122 8389,122 8365,146 8365,463
Neutral on Signal Layer 2 "Signal Layer 1-No Net 3" (solid, pour order 995): 7620,211 7739,211 7748,202 7748,98 7735,85 7619,85 7605,99 7605,196
Neutral on Signal Layer 2 "Signal Layer 1-No Net 3" (solid, pour order 996): 7620,211 7739,211 7748,202 7748,98 7735,85 7619,85 7605,99 7605,196
PGND on Signal Layer 2 "Bottom Layer-No Net 23" (solid, pour order 963): 5776,490 5741,525 5369,525 5369,332 5760,332 5776,348
AC_L1 on Signal Layer 4 "Top Layer-No Net 5" (solid, remove dead copper, pour order 967): 38 vertices, not listed, extent 1145,26 9329,1817
PGND on Signal Layer 4 "Signal Layer 4-PGND" (solid, pour order 1033): 20 vertices, not listed, extent 3541,1087 10794,2514
12VP on Signal Layer 4 "Bottom Layer-No Net 18" (solid, pour order 953): 10643,1698 10439.44,1698 10439.44,1508.44 10368,1437 6881,1437 6621.37,1696.63 6118.48,1696.63 6118.48,1200 10166,1200 10311,1055 10311,796 10739,796 10739,1035 10643,1131 10643,1347.51
AC_N1 on Signal Layer 4 "Signal Layer 4-No Net" (solid, pour order 1079): 2583,1060 2733,1060 2733,1372 2583,1372
EARTH on Signal Layer 4 "Top Layer-No Net 16" (solid, pour order 1074): 0,2125 0,1622 292,1622 292,2125
SW1 on Signal Layer 4 "Signal Layer 4-No Net" (solid, pour order 1071): 2514.23,393.28 2514.23,259.28 2826.23,259.28 2826.23,393.28
PGND on Signal Layer 4 "Signal Layer 4-No Net" (solid, pour order 1050): 7611,1012 7611,878 7923,878 7923,1012
Neutral on Signal Layer 4 "Signal Layer 4-No Net" (solid, pour order 1049): 4339,1226 4339,1092 4651,1092 4651,1226
PGND on Signal Layer 4 "Signal Layer 4-No Net" (solid, pour order 1048): 5375,521 5375,387 5687,387 5687,521
SW1 on Signal Layer 4 "NONET_L-01_P-001" (solid, pour order 1047): 4604,485 5053,485 5092,524 5290.64,524 5334,480.64 5334,338 5272,276 4604,276
Vcb on Signal Layer 4 "Bottom Layer-No Net 27" (solid, pour order 1010): 8534,442 8717,442 8717,261 8534,261
AC_N on Signal Layer 4 "Top Layer-No Net 8" (solid, remove dead copper, pour order 948): 2130,1747 1764,1747 1712,1695 1712,1398 1762,1348 1910,1200 2196,1200 2248,1252 2248,1629
Vbulk on Signal Layer 4 "Signal Layer 4-No Net" (solid, pour order 1002): 7202,1017 7171,986 7171,909 7205,875 7420,875 7461,916 7461,965 7409,1017
Neutral on Signal Layer 4 "Signal Layer 4-Neutral" (solid, remove dead copper, pour order 1030): 22 vertices, not listed, extent 2747,15 7776,1381
Vbulk_out on Signal Layer 4 "NONET_L-01_P-001" (solid, pour order 934): 4879,1858 4879,1673 4913.84,1638.16 5844.16,1638.16 5904,1698 5904,1840 5833,1911 4932,1911
Vbulk on Signal Layer 4 "NONET_L-01_P-001" (solid, pour order 937): 4857,1216 4948,1307 5759,1307 5815,1251 5815,1103 5753,1041 5743,1051 4939,1051 4857,1133
SW2 on Signal Layer 4 "Top Layer-No Net 2" (solid, remove dead copper, pour order 1036): 9978,1208 8300.2,1208 8114.2,1022 8007,1022 7952.35,967.35 7952.35,860.15 8028.5,784 8759.5,784 9991,784 10162,955 10162,1024
L_Wire on Signal Layer 4 "Top Layer-No Net 7" (solid, remove dead copper, pour order 944): 1291,2543 1355,2479 1355,2298 1267,2210 849,2210 720,2339 720,2514 749,2543
N_Wire on Signal Layer 4 "Top Layer-No Net 6" (solid, remove dead copper, pour order 945): 25 vertices, not listed, extent 101,1411 1341,2514
AC_L on Signal Layer 4 "Top Layer-No Net 9" (solid, remove dead copper, pour order 955): 19 vertices, not listed, extent 1132.5,1110 2241,2535
AC_N1 on Signal Layer 4 "Top Layer-No Net 16" (solid, pour order 973): 2000,712 2000,300 2050,250 2214,250 2272,308 2272,708 2202,778 2066,778
Vbulk on Signal Layer 4 "Signal Layer 4-No Net" (solid, pour order 1018): 5847,515 5847,381 6159,381 6159,515
Vcb on Signal Layer 4 "Bottom Layer-No Net 21" (solid, remove dead copper, pour order 1005): 6895,176 7111,176 7111,131 6895,131
AGND on Signal Layer 1 "Signal Layer 1-PGND 1" (solid, pour order 1042): 21 vertices, not listed, extent 2578,830.37 8916,2514
PGND on Signal Layer 1 "Signal Layer 1-PGND 2" (solid, remove dead copper, pour order 1046): 30 vertices, not listed, extent 3731,320 10804,2014
Vbulk_out on Signal Layer 1 "Signal Layer 1-Vbulk_out" (solid, pour order 1039): 5896,1597 8172,1597 8640,2065 10790,2065 10790,2502 10732.94,2559.06 8103,2559.06 8103,2399 7655,1951 7651,1955 4931,1955 4865,1889 4865,1597 5309,1153 5452,1153
PGND on Signal Layer 1 "Signal Layer 1-PGND" (solid, pour order 1032): 4882,1984 4882,2270 7983,2270 7983,1984
EARTH on Signal Layer 1 "Signal Layer 4-No Net" (solid, pour order 1072): 3.98,2127.34 3.98,1613 323,1613 323,2127.34
SW2 on Signal Layer 1 "Signal Layer 4-No Net" (solid, pour order 1059): 9871.49,1063.56 9871.49,916.94 10166.81,916.94 10166.81,1063.56
AC_N1 on Signal Layer 1 "Signal Layer 4-No Net" (solid, pour order 1058): 2575,1403 2575,1072 2743,1072 2743,1403
Neutral on Signal Layer 1 "Signal Layer 4-No Net" (solid, pour order 1057): 2768.68,1390 2768.68,1030 2985,1030 2985,1390
Neutral on Signal Layer 1 "Signal Layer 4-No Net" (solid, pour order 1056): 3533.68,265 3533.68,71 3728,71 3728,265
SW2 on Signal Layer 1 "Signal Layer 4-No Net" (solid, pour order 1055): 8368.68,1100 8368.68,867 8664,867 8664,1100
SW2 on Signal Layer 1 "Signal Layer 4-No Net" (solid, pour order 1054): 7954.68,1021 7954.68,874.38 8250,874.38 8250,1021
Vbulk on Signal Layer 1 "Signal Layer 4-No Net" (solid, pour order 1053): 4868.68,1231 4868.68,1084.38 5164,1084.38 5164,1231
Neutral on Signal Layer 1 "Signal Layer 4-No Net" (solid, pour order 1052): 4353,1220 4353,1098 4639,1098 4639,1220
SW1 on Signal Layer 1 "Top Layer-No Net 1" (solid, remove dead copper, pour order 1043): 5327.59,352.28 5326.99,468.66 5251.65,544 3766.35,544 3098.51,544 2494.01,544 2494.01,24 3308.01,24 3577.01,293 3926.96,293 4022.99,389.02 4149.99,389.02 4246.01,293 5268.31,293
Vcb on Signal Layer 1 "Top Layer-No Net 11" (solid, remove dead copper, pour order 976): 8717,501 8751,467 8751,111 8645,5 6824,5 5861,5 3975,5 3975,372 4135,372 4252,255 6895,255 7141,501
Neutral on Signal Layer 1 "Top Layer-No Net 19" (solid, pour order 943): 6082,184 6341,184 6341,132 6082,132
L_Wire on Signal Layer 1 "Top Layer-No Net 7" (solid, remove dead copper, pour order 946): 1291,2543 1355,2479 1355,2298 1267,2210 849,2210 720,2339 720,2514 749,2543
N_Wire on Signal Layer 1 "Top Layer-No Net 6" (solid, remove dead copper, pour order 950): 25 vertices, not listed, extent 101,1411 1341,2514
AC_N on Signal Layer 1 "Top Layer-No Net 8" (solid, remove dead copper, pour order 956): 2133,1747 1767,1747 1715,1695 1715,1398 1765,1348 1949,1164 2266.36,1164 2348,1245.64 2348,1532
AC_L on Signal Layer 1 "Top Layer-No Net 9" (solid, remove dead copper, pour order 960): 19 vertices, not listed, extent 1131,1111 2239.5,2536
AC_L1 on Signal Layer 1 "Top Layer-No Net 5" (solid, remove dead copper, pour order 965): 21 vertices, not listed, extent 1145,212 3631,1092
AC_N1 on Signal Layer 1 "Top Layer-No Net 16" (solid, pour order 966): 2000,712 2000,300 2050,250 2214,250 2272,308 2272,708 2202,778 2066,778
AC_L1 on Signal Layer 1 "Top Layer-No Net 20" (solid, pour order 1016): 9092,409 9518,409 9599,328 9599,183 9547,131 9121,131 9060,192 9060,377
Vbulk on Signal Layer 1 "Signal Layer 4-No Net" (solid, pour order 1017): 5837.68,528 5837.68,381.38 6133,381.38 6133,528
Vbulk on Signal Layer 1 "Signal Layer 4-No Net" (solid, pour order 1008): 7184.1,1028.1 7163,1007 7163,923 7203,883 7416,883 7461,928 7461,987 7419.9,1028.1
Neutral on Signal Layer 1 "Signal Layer 1-No Net 3" (solid, pour order 939): 7620,211 7739,211 7739,98 7606,98 7606,197
12VP on Signal Layer 3 "NONET_L-01_P-001" (solid, pour order 1027): 7519,1348 7446,1275 7059,1275 6985,1201 6881,1097 6881,1010 7048,1010 7071,1033 7071,1178 7084,1191 7515,1191 7578,1254 7578,1348
AGND on Signal Layer 3 "Signal Layer 3-PGND" (solid, pour order 1019): 45 vertices, not listed, extent 5919,337 10797,1633
PGND on Signal Layer 3 "Signal Layer 3-PGND 1" (solid, pour order 1041): 45 vertices, not listed, extent 3218,380 10626,2506
AGND on Signal Layer 3 "Signal Layer 3-PGND 2" (solid, pour order 1040): 2535,1477 3200,1477 3200,2506 2535,2506
12VP on Signal Layer 3 "NONET_L-01_P-001" (solid, pour order 1026): 20 vertices, not listed, extent 4642,333 6408,2043
EARTH on Signal Layer 3 "Bottom Layer-No Net 23" (solid, pour order 1073): 298,2123.16 7.06,2123.16 7.06,1614 298,1614
Neutral on Signal Layer 3 "Bottom Layer-No Net 23" (solid, pour order 1070): 3725,263.16 3532.06,263.16 3532.06,74 3725,74
Neutral on Signal Layer 3 "Bottom Layer-No Net 23" (solid, pour order 1069): 2980,1389.16 2768.06,1389.16 2768.06,1007 2980,1007
Neutral on Signal Layer 3 "Bottom Layer-No Net 23" (solid, pour order 1068): 4623.56,1217 4356,1217 4356,1087 4623.56,1087
AC_L1 on Signal Layer 3 "Bottom Layer-No Net 23" (solid, pour order 1067): 3606.56,1048 3339,1048 3339,918 3606.56,918
Vbulk_out on Signal Layer 3 "Bottom Layer-No Net 13" (solid, pour order 970): 8319.06,2559.06 8112,2352 8112,2113 7952,1953 7658,1953 7548,1843 7548,1725 7598,1675 8108,1675 8498,2065 10790,2065 10790,2502 10732.94,2559.06
SW1 on Signal Layer 3 "Top Layer-No Net 1" (solid, remove dead copper, pour order 1044): 5342.23,342.28 5341.64,458.66 5266.29,534 3781,534 3113.16,534 2508.66,534 2508.66,14 3322.66,14 3591.66,283 3941.61,283 4037.63,379.02 4164.63,379.02 4260.66,283 5282.96,283
PGND on Signal Layer 3 "Bottom Layer-No Net 23" (solid, pour order 968): 7917.78,1027 7651,1027 7611,987 7611,928 7662,877 7916.74,877
Vcb on Signal Layer 3 "Top Layer-No Net 11" (solid, remove dead copper, pour order 1000): 22 vertices, not listed, extent 3969.6,5 8750,623
Vbulk on Signal Layer 3 "Signal Layer 2-No Net 5" (solid, pour order 988): 5272.17,1028.83 4832,1033.81 4832,1311 5215,1311 5357,1169 5469,1169 5611,1311 5773,1311 5773,954 6205,522 6205,347 5854,347 5854,447
Vbulk_out on Signal Layer 3 "NONET_L-01_P-001" (solid, pour order 1034): 4879,1660 4872.33,1666.67 4872.33,1875.22 5834.78,1875.22 5868.17,1841.83 5868.17,1663.32 5817.85,1613 5792,1613 5792,1490.61 5457.59,1156.2 5386.8,1156.2 4871,1672
SW2 on Signal Layer 3 "Top Layer-No Net 2" (solid, remove dead copper, pour order 1031): 10093,1217 8198,1217 8029,1048 7955,974 7955,891 8036,810 8767,810 10072,810 10162,900 10162,1148
L_Wire on Signal Layer 3 "Top Layer-No Net 7" (solid, remove dead copper, pour order 935): 1291,2543 1355,2479 1355,2298 1267,2210 849,2210 720,2339 720,2514 749,2543
N_Wire on Signal Layer 3 "Top Layer-No Net 6" (solid, remove dead copper, pour order 938): 25 vertices, not listed, extent 101,1411 1341,2514
AC_N on Signal Layer 3 "Top Layer-No Net 8" (solid, remove dead copper, pour order 941): 2133,1747 1767,1747 1715,1695 1715,1398 1765,1348 1949,1164 2266.36,1164 2348,1245.64 2348,1532
AC_L on Signal Layer 3 "Top Layer-No Net 9" (solid, remove dead copper, pour order 947): 19 vertices, not listed, extent 1131,1111 2239.5,2536
AC_N1 on Signal Layer 3 "Bottom Layer-No Net 3" (solid, remove dead copper, pour order 951): 2506.36,1404 2479,1376.64 2479,1278 1959,758 1959,308 2056,211 2240,211 2293,264 2293,586 2723,1016 2723,1404
AC_L1 on Signal Layer 3 "Bottom Layer-No Net 20" (solid, pour order 958): 1184,824.5 1337,824.5 1404,757.5 1404,279.5 1340,215.5 1198,215.5 1143,270.5 1143,783.5
AC_L1 on Signal Layer 3 "Top Layer-No Net 20" (solid, pour order 1006): 9092,409 9518,409 9599,328 9599,183 9547,131 9121,131 9060,192 9060,377
Vbulk on Signal Layer 3 "Signal Layer 4-No Net" (solid, pour order 975): 7191,1020 7151,980 7151,918 7194,875 7416,875 7461,920 7461,981 7422,1020
Neutral on Signal Layer 3 "Top Layer-No Net 19" (solid, pour order 999): 6082,185 6341,185 6341,124 6082,124
Neutral on Signal Layer 3 "Signal Layer 1-No Net 3" (solid, pour order 997): 7621,212 7740,212 7749,203 7749,99 7736,86 7620,86 7606,100 7606,197
Vcb on Signal Layer 3 "Bottom Layer-No Net 21" (solid, remove dead copper, pour order 992): 6895,188 7111,188 7140,159 7140,104 7119,83 6902,83 6878,107 6878,171
Vcb on Signal Layer 3 "Bottom Layer-No Net 21" (solid, remove dead copper, pour order 993): 6895,188 7111,188 7140,159 7140,104 7119,83 6902,83 6878,107 6878,171

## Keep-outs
Keep-Out Layer:
  text ".Layer_Name" at 577,-2658.49 h30

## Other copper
Top Layer:
  text ".Layer_Name" at 577,-2658.49 h30
Signal Layer 1:
  rectangle net Vbulk_out: 4911,1673 5080,1853
  rectangle net Vbulk_out: 7543,1668 7951,1882
  pour cut-out: 6148,1934 6148,1952 6161,1965 6182,1965 6196,1951 6196,1932 6184,1920 6162,1920
Signal Layer 2:
  rectangle net PGND: 7556,2071 7938,2250
  rectangle net Vbulk_out: 7544,1668 7952,1882
Signal Layer 3:
  rectangle net Vbulk_out: 4916,1679 5072,1850
  rectangle net Vbulk_out: 7544,1675 7952,1889
Signal Layer 4:
  rectangle net Vbulk_out: 7560,1677 7941,1854
  rectangle net Vbulk_out: 4910,1673 5081,1855
Bottom Layer:
  rectangle net PGND: 4914,2065 5072,2249
  rectangle net PGND: 7551,2065 7945,2252
  pour cut-out: 6148,1936 6148,1954 6161,1967 6182,1967 6196,1953 6196,1934 6184,1922 6162,1922
  text ".Layer_Name" at 577,-2658.49 h30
